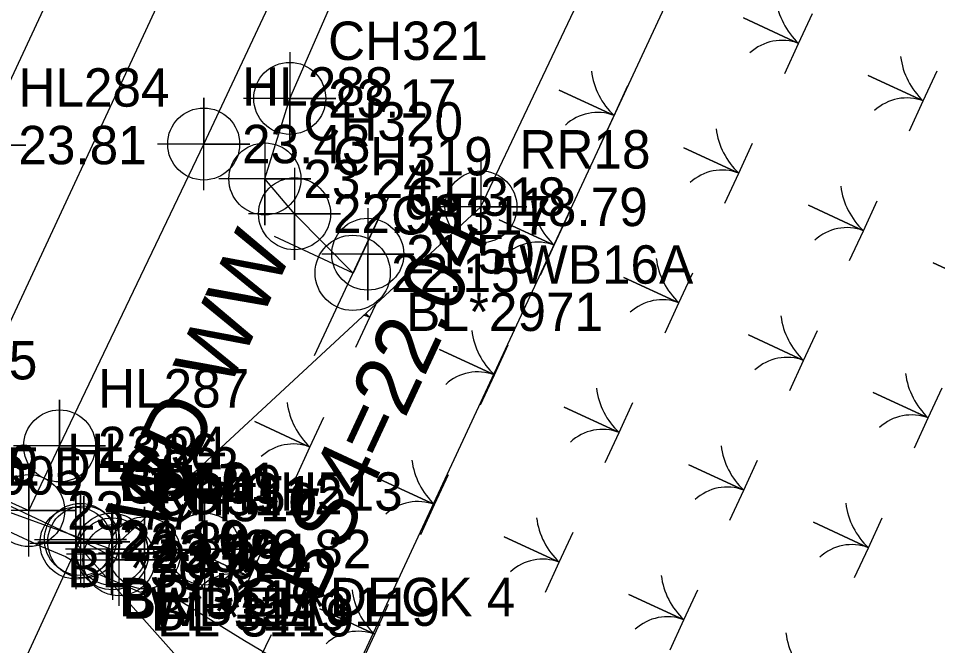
# Model space of a CAD drawing. Extents: x 2532037 to 2533565, y 713396 to 716867.
# Drawn here: x 2532881.8 to 2532941.6, y 715640.6 to 715681.4 of the extents above; entities that cross this region are included whole.
import ezdxf

# ---------------------------------------------------------------- set-up
doc = ezdxf.new("R2010")
doc.units = 0
for name, color, linetype in [('Exist Environmental Wetland Boundary', 7, 'Continuous'), ('Exist Environmental Wetland Boundary Cogo Comment', 7, 'Continuous'), ('Exist Environmental Wetland Boundary Cogo Elevation', 7, 'Continuous'), ('Exist Environmental Wetland Boundary Cogo Number', 7, 'Continuous'), ('Exist Environmental Wetland Boundary Cogo Point CELL', 7, 'Continuous'), ('Exist Horizontal Alignment', 7, 'Continuous'), ('Exist Hydro Jurisdictional Stream or Body of Water', 7, 'Continuous'), ('Exist Right of Way Line', 7, 'Continuous'), ('Exist Roads Soil', 7, 'Continuous'), ('Exist Roads Soil Cogo Comment', 7, 'Continuous'), ('Exist Roads Soil Cogo Elevation', 7, 'Continuous'), ('Exist Roads Soil Cogo Number', 7, 'Continuous'), ('Exist Roads Soil Cogo Point CELL', 7, 'Continuous'), ('Exist Structure Major Bridge Seat Cogo Point CELL', 7, 'Continuous'), ('Exist Structure Major Bridge Seat Leader', 7, 'Continuous'), ('Exist Structure Major Bridge Seat Top Elevation', 7, 'Continuous'), ('Exist Structure Major Bridge WW', 7, 'Continuous'), ('Exist Structure Major Bridge WW Cogo Comment', 7, 'Continuous'), ('Exist Structure Major Bridge WW Cogo Elevation', 7, 'Continuous'), ('Exist Structure Major Bridge WW Cogo Number', 7, 'Continuous'), ('Exist Structure Major Bridge WW Cogo Point CELL', 7, 'Continuous'), ('Exist Structure Major Bridge WW Text', 7, 'Continuous'), ('Exist Structure Major Deck Tunnel Box Culvert', 7, 'Continuous'), ('Exist Structure Major Deck Tunnel Box Culvert Cogo Comment', 7, 'Continuous'), ('Exist Structure Major Deck Tunnel Box Culvert Cogo Elevation', 7, 'Continuous'), ('Exist Structure Major Deck Tunnel Box Culvert Cogo Number', 7, 'Continuous'), ('Exist Structure Major Deck Tunnel Box Culvert Cogo Point CELL', 7, 'Continuous'), ('Exist Utilities Power Joint Use Telephone CELL', 7, 'Continuous'), ('Exist Utilities Power Joint Use Telephone Cogo Elevation', 7, 'Continuous'), ('Exist Utilities Power Joint Use Telephone Cogo Number', 7, 'Continuous'), ('Exist Utilities Telephone UG Cable SUE LOS B Cogo Comment', 7, 'Continuous'), ('Exist Utilities Telephone UG Cable SUE LOS B Cogo Elevation', 7, 'Continuous'), ('Exist Utilities Telephone UG Cable SUE LOS B Cogo Number', 7, 'Continuous'), ('Exist Utilities Telephone UG Cable SUE LOS B Cogo Point CELL', 7, 'Continuous'), ('Exist Utilities Telephone UG Cable SUE LOS C', 7, 'Continuous'), ('Scratch_Level_1', 7, 'Continuous')]:
    doc.layers.add(name, color=color, linetype=linetype)

msp = doc.modelspace()

# ---------------------------------------------------------------- linework, layer by layer
at = {"layer": 'Exist Environmental Wetland Boundary'}
for p, q in [((2532911.894, 715669.143), (2532945.52, 715740.024)), ((2532887.83, 715646.863), (2532911.894, 715669.143)), ((2532867.338, 715654.282), (2532887.83, 715646.863))]:
    msp.add_line(p, q, dxfattribs=at)
at = {"layer": 'Exist Environmental Wetland Boundary Cogo Point CELL'}
for points in [[(2532911.894, 715672.143), (2532911.894, 715666.143), (2532911.894, 715669.143), (2532914.894, 715669.143), (2532908.894, 715669.143)], [(2532887.83, 715649.863), (2532887.83, 715643.863), (2532887.83, 715646.863), (2532890.83, 715646.863), (2532884.83, 715646.863)]]:
    msp.add_lwpolyline(points, dxfattribs=at)
for centre in [(2532911.894, 715669.143), (2532887.83, 715646.863)]:
    msp.add_circle(centre, 2.344, dxfattribs=at)
at = {"layer": 'Exist Horizontal Alignment'}
msp.add_line((2532720.816, 715316.862), (2532922.836, 715751.084), dxfattribs=at)
at = {"layer": 'Exist Hydro Jurisdictional Stream or Body of Water'}
msp.add_lwpolyline([(2532806.944, 715649.86), (2532823.862, 715653.608), (2532826.936, 715654.78), (2532846.795, 715657.486), (2532848.935, 715657.763), (2532859.818, 715661.557), (2532865.255, 715655.34), (2532866.545, 715654.873), (2532867.828, 715654.527), (2532870.349, 715653.031), (2532883.272, 715647.025), (2532884.83, 715646.372), (2532885.882, 715645.762), (2532886.539, 715645.426), (2532889.693, 715644.068), (2532889.952, 715644.137), (2532891.522, 715643.982), (2532891.782, 715643.826), (2532896.496, 715640.921), (2532907.078, 715634.646), (2532915.587, 715630.595), (2532919.574, 715628.211), (2532929.47, 715622.835), (2532946.956, 715616.792)], dxfattribs=at)
at = {"layer": 'Exist Right of Way Line'}
msp.add_line((2532748.017, 715304.207), (2532950.036, 715738.429), dxfattribs=at)
at = {"layer": 'Exist Roads Soil'}
for points in [[(2533033.002, 715963.552), (2533014.441, 715935.484), (2532992.666, 715901.095), (2532976.471, 715871.314), (2532962.05, 715845.129), (2532943.271, 715807.995), (2532921.982, 715764.363), (2532902.685, 715724.284), (2532889.068, 715694.204), (2532879.255, 715673.169), (2532870.648, 715655.411), (2532876.571, 715652.013), (2532882.435, 715649.375)], [(2532882.435, 715649.375), (2532884.446, 715653.582), (2532893.832, 715673.236), (2532904.082, 715695.07), (2532909.886, 715707.279), (2532923.655, 715737.545), (2532935.371, 715761.586), (2532947.639, 715787.122), (2532960.723, 715812.473), (2532979.299, 715846.297), (2532995.343, 715875.457), (2533008.573, 715897.69), (2533027.701, 715928.616), (2533038.596, 715945.654), (2533044.798, 715955.275)]]:
    msp.add_lwpolyline(points, dxfattribs=at)
at = {"layer": 'Exist Roads Soil Cogo Point CELL'}
for points in [[(2532879.255, 715670.169), (2532879.255, 715676.169), (2532879.255, 715673.169), (2532882.255, 715673.169), (2532876.255, 715673.169)], [(2532893.832, 715670.236), (2532893.832, 715676.236), (2532893.832, 715673.236), (2532896.832, 715673.236), (2532890.832, 715673.236)], [(2532884.446, 715650.582), (2532884.446, 715656.582), (2532884.446, 715653.582), (2532887.446, 715653.582), (2532881.446, 715653.582)], [(2532882.435, 715646.375), (2532882.435, 715652.375), (2532882.435, 715649.375), (2532885.435, 715649.375), (2532879.435, 715649.375)]]:
    msp.add_lwpolyline(points, dxfattribs=at)
for centre in [(2532893.832, 715673.236), (2532884.446, 715653.582), (2532882.435, 715649.375)]:
    msp.add_circle(centre, 2.344, dxfattribs=at)
at = {"layer": 'Exist Structure Major Bridge Seat Cogo Point CELL'}
msp.add_lwpolyline([(2532882.513, 715647.26), (2532888.513, 715647.26), (2532885.513, 715647.26), (2532885.513, 715650.26), (2532885.513, 715644.26)], dxfattribs=at)
msp.add_lwpolyline([(2532882.513, 715647.26), (2532888.513, 715647.26), (2532885.513, 715647.26), (2532885.513, 715650.26), (2532885.513, 715644.26)], dxfattribs=at)
msp.add_circle((2532885.513, 715647.26), 2.344, dxfattribs=at)
msp.add_circle((2532885.513, 715647.26), 2.344, dxfattribs=at)
at = {"layer": 'Exist Structure Major Bridge Seat Leader'}
msp.add_lwpolyline([(2532885.513, 715647.26), (2532895.617, 715635.909), (2532898.253, 715641.299)], dxfattribs=at)
at = {"layer": 'Exist Structure Major Bridge WW'}
msp.add_line((2532886.02, 715647.333), (2532888.308, 715646.174), dxfattribs=at)
msp.add_lwpolyline([(2532887.896, 715646.555), (2532889.982, 715646.62), (2532893.891, 715646.864)], dxfattribs=at)
at = {"layer": 'Exist Structure Major Bridge WW Cogo Point CELL'}
for points in [[(2532883.02, 715647.333), (2532889.02, 715647.333), (2532886.02, 715647.333), (2532886.02, 715650.333), (2532886.02, 715644.333)], [(2532884.896, 715646.555), (2532890.896, 715646.555), (2532887.896, 715646.555), (2532887.896, 715649.555), (2532887.896, 715643.555)], [(2532886.982, 715646.62), (2532892.982, 715646.62), (2532889.982, 715646.62), (2532889.982, 715649.62), (2532889.982, 715643.62)], [(2532890.891, 715646.864), (2532896.891, 715646.864), (2532893.891, 715646.864), (2532893.891, 715649.864), (2532893.891, 715643.864)], [(2532885.308, 715646.174), (2532891.308, 715646.174), (2532888.308, 715646.174), (2532888.308, 715649.174), (2532888.308, 715643.174)]]:
    msp.add_lwpolyline(points, dxfattribs=at)
for centre in [(2532886.02, 715647.333), (2532889.982, 715646.62), (2532893.891, 715646.864), (2532887.896, 715646.555), (2532888.308, 715646.174)]:
    msp.add_circle(centre, 2.344, dxfattribs=at)
at = {"layer": 'Exist Structure Major Deck Tunnel Box Culvert'}
msp.add_lwpolyline([(2532885.805, 715647.494), (2532867.812, 715655.999), (2532853.101, 715623.682), (2532870.979, 715615.38), (2532885.805, 715647.494)], dxfattribs=at)
at = {"layer": 'Exist Structure Major Deck Tunnel Box Culvert Cogo Point CELL'}
msp.add_lwpolyline([(2532882.805, 715647.494), (2532888.805, 715647.494), (2532885.805, 715647.494), (2532885.805, 715650.494), (2532885.805, 715644.494)], dxfattribs=at)
msp.add_lwpolyline([(2532882.805, 715647.494), (2532888.805, 715647.494), (2532885.805, 715647.494), (2532885.805, 715650.494), (2532885.805, 715644.494)], dxfattribs=at)
msp.add_circle((2532885.805, 715647.494), 2.344, dxfattribs=at)
msp.add_circle((2532885.805, 715647.494), 2.344, dxfattribs=at)
at = {"layer": 'Exist Utilities Power Joint Use Telephone CELL'}
msp.add_line((2532903.546, 715664.845), (2532903.546, 715664.845), dxfattribs=at)
msp.add_lwpolyline([(2532901.041, 715659.462), (2532905.857, 715669.725), (2532903.563, 715664.837), (2532898.446, 715667.218)], dxfattribs=at)
msp.add_circle((2532903.54, 715664.849), 2.45, dxfattribs=at)
at = {"layer": 'Exist Utilities Telephone UG Cable SUE LOS B Cogo Point CELL'}
for points in [[(2532899.436, 715679.209), (2532899.436, 715673.209), (2532899.436, 715676.209), (2532902.436, 715676.209), (2532896.436, 715676.209)], [(2532897.819, 715673.962), (2532897.819, 715667.962), (2532897.819, 715670.962), (2532900.819, 715670.962), (2532894.819, 715670.962)], [(2532899.751, 715671.696), (2532899.751, 715665.696), (2532899.751, 715668.696), (2532902.751, 715668.696), (2532896.751, 715668.696)], [(2532904.521, 715669.065), (2532904.521, 715663.065), (2532904.521, 715666.065), (2532907.521, 715666.065), (2532901.521, 715666.065)]]:
    msp.add_lwpolyline(points, dxfattribs=at)
for centre in [(2532899.436, 715676.209), (2532897.819, 715670.962), (2532899.751, 715668.696), (2532904.521, 715666.065)]:
    msp.add_circle(centre, 2.344, dxfattribs=at)
at = {"layer": 'Exist Utilities Telephone UG Cable SUE LOS C'}
msp.add_lwpolyline([(2532903.546, 715664.845), (2532899.751, 715668.696), (2532897.819, 715670.962), (2532899.436, 715676.209), (2532904.794, 715688.417), (2532912.91, 715705.872), (2532926.672, 715736.124), (2532938.373, 715760.133), (2532950.625, 715785.635), (2532963.667, 715810.905), (2532982.222, 715844.69), (2532998.238, 715873.8), (2533011.425, 715895.96), (2533023.694, 715915.797)], dxfattribs=at)
at = {"layer": 'Scratch_Level_1'}
for points in [[(2532931.687, 715677.837), (2532932.588, 715679.789), (2532929.006, 715681.443), (2532932.588, 715679.789), (2532933.489, 715681.741)], [(2532939.808, 715674.087), (2532940.709, 715676.04), (2532937.127, 715677.693), (2532940.709, 715676.04), (2532941.611, 715677.992)], [(2532919.667, 715673.142), (2532920.568, 715675.094), (2532916.986, 715676.748), (2532920.568, 715675.094), (2532921.469, 715677.046)], [(2532927.788, 715669.392), (2532928.689, 715671.345), (2532925.108, 715672.998), (2532928.689, 715671.345), (2532929.591, 715673.297)], [(2532935.91, 715665.643), (2532936.811, 715667.595), (2532933.229, 715669.249), (2532936.811, 715667.595), (2532937.712, 715669.548)], [(2532915.768, 715664.697), (2532916.67, 715666.65), (2532913.088, 715668.303), (2532916.67, 715666.65), (2532917.571, 715668.602)], [(2532944.031, 715661.894), (2532944.932, 715663.846), (2532941.35, 715665.5), (2532944.932, 715663.846), (2532945.834, 715665.798)], [(2532923.89, 715660.948), (2532924.791, 715662.9), (2532921.209, 715664.554), (2532924.791, 715662.9), (2532925.692, 715664.853)], [(2532904.303, 715662.115), (2532904.65, 715661.955), (2532905.038, 715662.795)], [(2532903.748, 715660.002), (2532904.65, 715661.955), (2532904.303, 715662.115)], [(2532932.011, 715657.199), (2532932.912, 715659.151), (2532929.331, 715660.805), (2532932.912, 715659.151), (2532933.814, 715661.103)], [(2532911.87, 715656.253), (2532912.771, 715658.205), (2532909.189, 715659.859), (2532912.771, 715658.205), (2532913.672, 715660.158)], [(2532940.133, 715653.449), (2532941.034, 715655.402), (2532937.452, 715657.055), (2532941.034, 715655.402), (2532941.935, 715657.354)], [(2532919.991, 715652.504), (2532920.893, 715654.456), (2532917.311, 715656.11), (2532920.893, 715654.456), (2532921.794, 715656.408)], [(2532899.85, 715651.558), (2532900.751, 715653.51), (2532897.169, 715655.164), (2532900.751, 715653.51), (2532901.653, 715655.463)], [(2532928.113, 715648.754), (2532929.014, 715650.707), (2532925.432, 715652.36), (2532929.014, 715650.707), (2532929.915, 715652.659)], [(2532907.971, 715647.809), (2532908.873, 715649.761), (2532905.291, 715651.415), (2532908.873, 715649.761), (2532909.774, 715651.713)], [(2532936.234, 715645.005), (2532937.135, 715646.957), (2532933.554, 715648.611), (2532937.135, 715646.957), (2532938.037, 715648.91)], [(2532916.093, 715644.059), (2532916.994, 715646.012), (2532913.412, 715647.665), (2532916.994, 715646.012), (2532917.895, 715647.964)], [(2532895.951, 715643.114), (2532896.853, 715645.066), (2532893.271, 715646.72), (2532896.853, 715645.066), (2532897.754, 715647.018)], [(2532924.214, 715640.31), (2532925.116, 715642.262), (2532921.534, 715643.916), (2532925.116, 715642.262), (2532926.017, 715644.215)], [(2532904.073, 715639.364), (2532904.974, 715641.317), (2532901.392, 715642.97), (2532904.974, 715641.317), (2532905.876, 715643.269)]]:
    msp.add_lwpolyline(points, dxfattribs=at)
for centre, radius, start, end in [((2532935.875, 715683.295), 4.806, 187.34643, 226.84116), ((2532931.504, 715676.912), 3.075, 69.35932, 132.75394), ((2532943.997, 715679.545), 4.806, 187.34643, 226.84116), ((2532923.855, 715678.6), 4.806, 187.34643, 226.84116), ((2532939.626, 715673.162), 3.075, 69.35932, 132.75394), ((2532919.484, 715672.217), 3.075, 69.35932, 132.75394), ((2532931.977, 715674.85), 4.806, 187.34643, 226.84116), ((2532927.606, 715668.467), 3.075, 69.35932, 132.75394), ((2532940.098, 715671.101), 4.806, 187.34643, 226.84116), ((2532919.957, 715670.155), 4.806, 187.34643, 226.84116), ((2532935.727, 715664.718), 3.075, 69.35932, 132.75394), ((2532915.586, 715663.772), 3.075, 69.35932, 132.75394), ((2532928.078, 715666.406), 4.806, 187.34643, 226.84116), ((2532923.707, 715660.023), 3.075, 69.35932, 132.75394), ((2532907.937, 715665.46), 4.806, 222.62971, 226.84116), ((2532903.566, 715659.078), 3.075, 69.35932, 76.98905), ((2532936.2, 715662.657), 4.806, 187.34643, 226.84116), ((2532916.058, 715661.711), 4.806, 187.34643, 226.84116), ((2532931.829, 715656.274), 3.075, 69.35932, 132.75394), ((2532911.687, 715655.328), 3.075, 69.35932, 132.75394), ((2532944.321, 715658.907), 4.806, 187.34643, 226.84116), ((2532924.18, 715657.962), 4.806, 187.34643, 226.84116), ((2532904.038, 715657.016), 4.806, 187.34643, 226.84116), ((2532939.95, 715652.524), 3.075, 69.35932, 132.75394), ((2532919.809, 715651.579), 3.075, 69.35932, 132.75394), ((2532899.667, 715650.633), 3.075, 69.35932, 132.75394), ((2532932.301, 715654.212), 4.806, 187.34643, 226.84116), ((2532912.16, 715653.267), 4.806, 187.34643, 226.84116), ((2532927.93, 715647.829), 3.075, 69.35932, 132.75394), ((2532907.789, 715646.884), 3.075, 69.35932, 132.75394), ((2532940.423, 715650.463), 4.806, 187.34643, 226.84116), ((2532920.281, 715649.517), 4.806, 187.34643, 226.84116), ((2532900.14, 715648.572), 4.806, 187.34643, 226.84116), ((2532936.052, 715644.08), 3.075, 69.35932, 132.75394), ((2532915.91, 715643.134), 3.075, 69.35932, 132.75394), ((2532895.769, 715642.189), 3.075, 69.35932, 132.75394), ((2532928.403, 715645.768), 4.806, 187.34643, 226.84116), ((2532908.261, 715644.822), 4.806, 187.34643, 226.84116), ((2532924.032, 715639.385), 3.075, 69.35932, 132.75394), ((2532903.89, 715638.439), 3.075, 69.35932, 132.75394), ((2532936.524, 715642.018), 4.806, 187.34643, 226.84116)]:
    msp.add_arc(centre, radius, start, end, dxfattribs=at)

# ---------------------------------------------------------------- texts
at = {"layer": 'Exist Environmental Wetland Boundary Cogo Comment'}
for s, p in [('WB16A', (2532914.394, 715664.143)), ('WB15A', (2532890.33, 715641.863))]:
    msp.add_text(s, height=2.5, dxfattribs=at).set_placement(p)
at = {"layer": 'Exist Environmental Wetland Boundary Cogo Elevation'}
for s, p in [('18.79', (2532914.394, 715667.893)), ('23.49', (2532890.33, 715645.613))]:
    msp.add_text(s, height=2.5, dxfattribs=at).set_placement(p)
at = {"layer": 'Exist Environmental Wetland Boundary Cogo Number'}
for s, p in [('RR18', (2532914.394, 715671.643)), ('RR4', (2532890.33, 715649.363))]:
    msp.add_text(s, height=2.5, dxfattribs=at).set_placement(p)
at = {"layer": 'Exist Roads Soil Cogo Comment'}
for s, p in [('EL*3005', (2532873.148, 715650.411)), ('BL*3005', (2532884.935, 715644.375))]:
    msp.add_text(s, height=2.5, dxfattribs=at).set_placement(p)
at = {"layer": 'Exist Roads Soil Cogo Elevation'}
for s, p in [('23.81', (2532881.755, 715671.919)), ('23.43', (2532896.332, 715671.986)), ('23.94', (2532886.946, 715652.332)), ('23.77', (2532884.935, 715648.125))]:
    msp.add_text(s, height=2.5, dxfattribs=at).set_placement(p)
at = {"layer": 'Exist Roads Soil Cogo Number'}
for s, p in [('HL284', (2532881.755, 715675.669)), ('HL288', (2532896.332, 715675.736)), ('HL285', (2532873.148, 715657.911)), ('HL287', (2532886.946, 715656.082)), ('HL286', (2532884.935, 715651.875))]:
    msp.add_text(s, height=2.5, dxfattribs=at).set_placement(p)
at = {"layer": 'Exist Structure Major Bridge Seat Top Elevation'}
msp.add_text("BS4=22.04'", height=4, rotation=65.05, dxfattribs=at).set_placement((2532901.346, 715643.31))
at = {"layer": 'Exist Structure Major Bridge WW Cogo Comment'}
for s, p in [('BL*3119', (2532870.227, 715651.142)), ('BL*3119', (2532888.52, 715642.333)), ('EL*3119', (2532896.391, 715641.864)), ('BL*3119', (2532890.396, 715641.555)), ('EL*3119', (2532890.808, 715641.174))]:
    msp.add_text(s, height=2.5, dxfattribs=at).set_placement(p)
at = {"layer": 'Exist Structure Major Bridge WW Cogo Elevation'}
for s, p in [('23.89', (2532888.52, 715646.083)), ('23.95', (2532890.396, 715645.305)), ('23.91', (2532892.482, 715645.37)), ('20.82', (2532896.391, 715645.614)), ('23.92', (2532890.808, 715644.924))]:
    msp.add_text(s, height=2.5, dxfattribs=at).set_placement(p)
at = {"layer": 'Exist Structure Major Bridge WW Cogo Number'}
for s, p in [('CH509', (2532888.52, 715649.833)), ('CH511', (2532890.396, 715649.055)), ('CH512', (2532892.482, 715649.12)), ('CH513', (2532896.391, 715649.364)), ('CH510', (2532890.808, 715648.674))]:
    msp.add_text(s, height=2.5, dxfattribs=at).set_placement(p)
at = {"layer": 'Exist Structure Major Bridge WW Text'}
msp.add_text('WD WW', height=4, rotation=65.05, dxfattribs=at).set_placement((2532891.017, 715647.687))
at = {"layer": 'Exist Structure Major Deck Tunnel Box Culvert Cogo Comment'}
for s, p in [('BRIDGE DECK 3', (2532870.312, 715650.999)), ('BRIDGE DECK 4', (2532888.305, 715642.494))]:
    msp.add_text(s, height=2.5, dxfattribs=at).set_placement(p)
at = {"layer": 'Exist Structure Major Deck Tunnel Box Culvert Cogo Elevation'}
msp.add_text('24.10', height=2.5, dxfattribs=at).set_placement((2532888.305, 715646.244))
msp.add_text('24.10', height=2.5, dxfattribs=at).set_placement((2532888.305, 715646.244))
at = {"layer": 'Exist Structure Major Deck Tunnel Box Culvert Cogo Number'}
for s in ['CH501', 'BD4']:
    msp.add_text(s, height=2.5, dxfattribs=at).set_placement((2532888.305, 715649.994))
at = {"layer": 'Exist Utilities Power Joint Use Telephone Cogo Elevation'}
msp.add_text('22.15', height=2.5, dxfattribs=at).set_placement((2532906.046, 715663.595))
at = {"layer": 'Exist Utilities Power Joint Use Telephone Cogo Number'}
msp.add_text('CH317', height=2.5, dxfattribs=at).set_placement((2532906.046, 715667.345))
at = {"layer": 'Exist Utilities Telephone UG Cable SUE LOS B Cogo Comment'}
msp.add_text('BL*2971', height=2.5, dxfattribs=at).set_placement((2532907.021, 715661.065))
at = {"layer": 'Exist Utilities Telephone UG Cable SUE LOS B Cogo Elevation'}
for s, p in [('23.17', (2532901.936, 715674.959)), ('23.24', (2532900.319, 715669.712)), ('22.98', (2532902.251, 715667.446)), ('21.50', (2532907.021, 715664.815))]:
    msp.add_text(s, height=2.5, dxfattribs=at).set_placement(p)
at = {"layer": 'Exist Utilities Telephone UG Cable SUE LOS B Cogo Number'}
for s, p in [('CH321', (2532901.936, 715678.709)), ('CH320', (2532900.319, 715673.462)), ('CH319', (2532902.251, 715671.196)), ('CH318', (2532907.021, 715668.565))]:
    msp.add_text(s, height=2.5, dxfattribs=at).set_placement(p)

doc.saveas('drawing.dxf')
